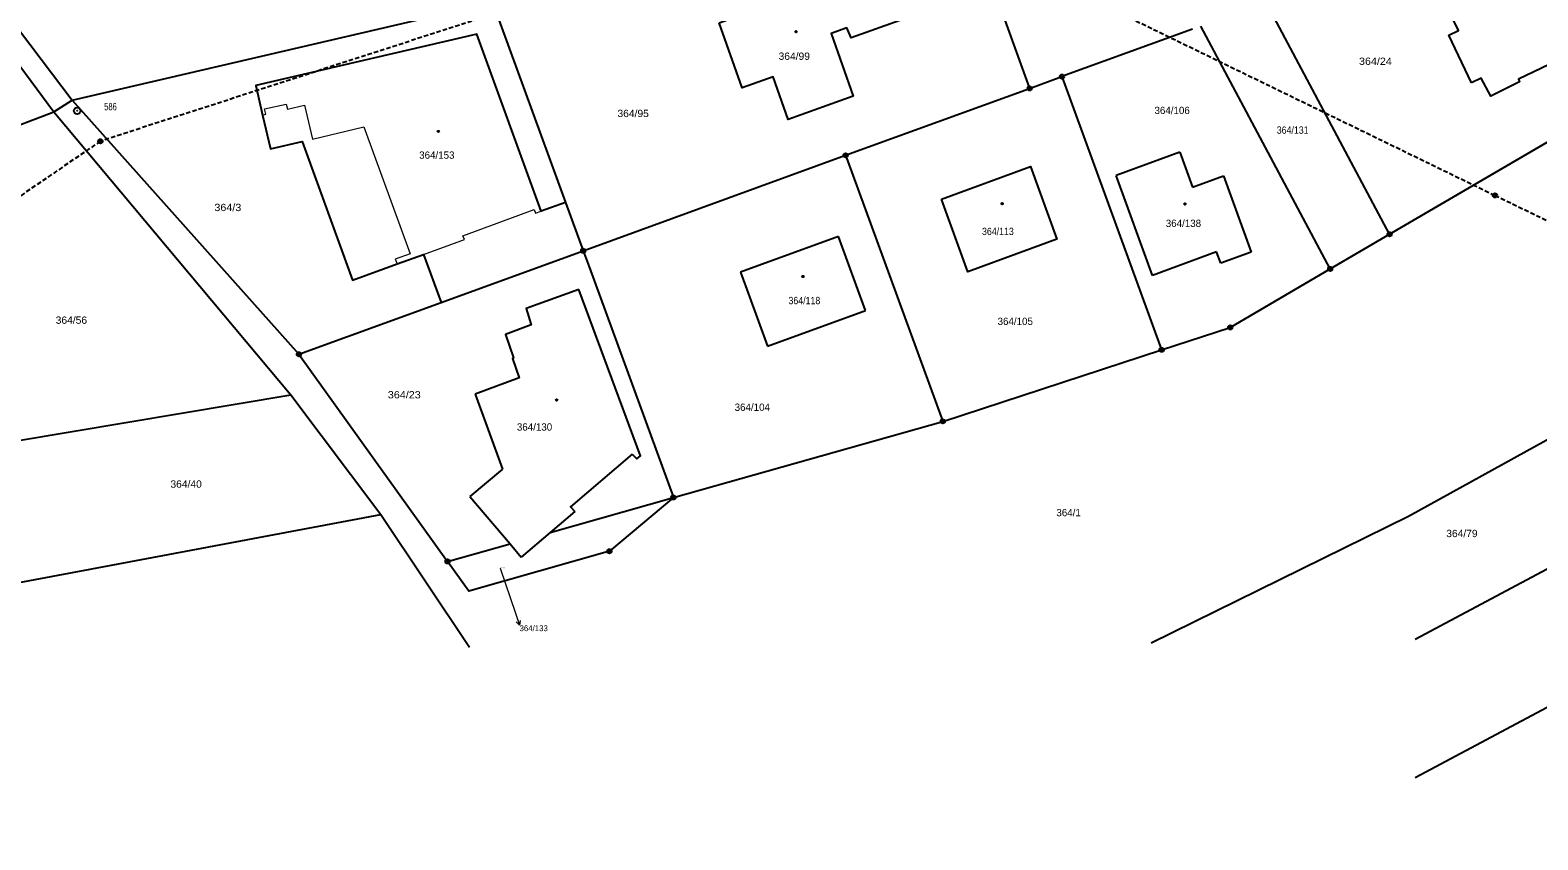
# Model space of a CAD drawing. Extents: x -592965 to -592390, y -1145071 to -1144631.
# Drawn here: x -592769.5 to -592594.1, y -1145071.2 to -1144977 of the extents above; entities that cross this region are included whole.
import ezdxf
from ezdxf.enums import TextEntityAlignment as Align

# ---------------------------------------------------------------- set-up
doc = ezdxf.new("R2010")
doc.units = 0
doc.header["$LTSCALE"] = 0.17
doc.linetypes.add('MEDIUM_DASHED', pattern=[4.5, 3, -1.5])
doc.layers.add('4', color=7, linetype='Continuous', lineweight=25)

msp = doc.modelspace()

# ---------------------------------------------------------------- linework, layer by layer
at = {"layer": '4'}
for p, q in [((-592662.36, -1144958.47), (-592653.19, -1144983.74)), ((-592775.53, -1144974.54), (-592766.72, -1144986.47)), ((-592618.23, -1145004.75), (-592633.27, -1144976.49)), ((-592634.25, -1144976.85), (-592649.43, -1144982.37)), ((-592674.6, -1144991.53), (-592653.19, -1144983.74)), ((-592653.19, -1144983.74), (-592649.43, -1144982.37)), ((-592649.43, -1144982.37), (-592637.84, -1145014.16)), ((-592766.72, -1144986.47), (-592764.58, -1144985.13)), ((-592764.58, -1144985.13), (-592738.2, -1145014.67)), ((-592784.27, -1144993.14), (-592766.72, -1144986.47)), ((-592766.72, -1144986.47), (-592739.14, -1145019.41)), ((-592611.32, -1145000.71), (-592591.61, -1144989.18)), ((-592705.13, -1145002.64), (-592674.6, -1144991.53)), ((-592635.71, -1144991.18), (-592643.11, -1144993.87)), ((-592635.71, -1144991.18), (-592634.23, -1144995.22)), ((-592638.9, -1145005.53), (-592643.11, -1144993.87)), ((-592634.23, -1144995.22), (-592630.65, -1144993.92)), ((-592630.65, -1144993.92), (-592627.42, -1145002.8)), ((-592707.19, -1144997), (-592710, -1144998.03)), ((-592675.42, -1145000.98), (-592686.83, -1145005.13)), ((-592672.29, -1145009.57), (-592675.42, -1145000.98)), ((-592631.45, -1145002.77), (-592638.9, -1145005.53)), ((-592630.96, -1145004.09), (-592631.45, -1145002.77)), ((-592627.42, -1145002.8), (-592630.96, -1145004.09)), ((-592686.83, -1145005.13), (-592683.7, -1145013.73)), ((-592683.7, -1145013.73), (-592672.29, -1145009.57)), ((-592738.2, -1145014.67), (-592720.91, -1145038.78)), ((-592771.06, -1145024.76), (-592739.14, -1145019.41)), ((-592739.14, -1145019.41), (-592728.67, -1145033.3)), ((-592717.7, -1145019.32), (-592714.53, -1145028.03)), ((-592608.34, -1145047.82), (-592558.85, -1145021.44)), ((-592714.53, -1145028.03), (-592718.31, -1145031.21)), ((-592608.36, -1145063.93), (-592546.61, -1145030.99)), ((-592718.31, -1145031.21), (-592713.63, -1145036.72)), ((-592708.98, -1145035.4), (-592694.63, -1145031.34)), ((-592819.84, -1145050.47), (-592728.67, -1145033.3)), ((-592728.67, -1145033.3), (-592718.36, -1145048.77)), ((-592706.11, -1145032.97), (-592708.98, -1145035.4)), ((-592708.98, -1145035.4), (-592712.36, -1145038.27)), ((-592720.91, -1145038.78), (-592713.63, -1145036.72)), ((-592713.63, -1145036.72), (-592712.36, -1145038.27))]:
    msp.add_line(p, q, dxfattribs=at)
at = {"layer": '4', "linetype": 'MEDIUM_DASHED'}
for points in [[(-592857.7, -1144647.96), (-592827.25, -1144698.04), (-592798.73, -1144745.3), (-592765.1, -1144800.74), (-592721.92, -1144873.86), (-592693.51, -1144920.47), (-592669.72, -1144961.82), (-592709.34, -1144973.09), (-592761.29, -1144989.89), (-592825.83, -1145034.08), (-592878.88, -1145071.17)], [(-592669.72, -1144961.82), (-592599.07, -1144996.19), (-592537.81, -1145025.68), (-592483.65, -1145051.69)]]:
    msp.add_lwpolyline(points, dxfattribs=at)
at = {"layer": '4'}
for points in [[(-592601.78, -1144983.1), (-592604.44, -1144977.55), (-592603.32, -1144977.01), (-592605.06, -1144973.35), (-592601, -1144971.39), (-592600.86, -1144971.68), (-592596.51, -1144969.57), (-592596.55, -1144969.48), (-592592.72, -1144967.63), (-592588.6, -1144976.22), (-592592.06, -1144977.86), (-592590.98, -1144980.12), (-592596.32, -1144982.68), (-592596.19, -1144982.99), (-592599.54, -1144984.65), (-592600.66, -1144982.55)], [(-592689.32, -1144976.1), (-592668.32, -1144968.52), (-592665.99, -1144975.02), (-592673.94, -1144977.88), (-592674.44, -1144976.7), (-592676.29, -1144977.37), (-592673.71, -1144984.65), (-592681.27, -1144987.36), (-592683.04, -1144982.4), (-592686.63, -1144983.68)], [(-592663.45, -1144996.63), (-592653.1, -1144992.84), (-592650.02, -1145001.3), (-592660.37, -1145005.08)]]:
    msp.add_lwpolyline(points, close=True, dxfattribs=at)
for points in [[(-592773.14, -1144973.83), (-592764.58, -1144985.13), (-592715.69, -1144973.75)], [(-592715.69, -1144973.75), (-592707.19, -1144997), (-592705.13, -1145002.64)], [(-592611.32, -1145000.71), (-592624.43, -1144976.07), (-592624.75, -1144975.48)], [(-592710, -1144998.03), (-592717.51, -1144977.44), (-592743.21, -1144983.42), (-592742.44, -1144986.84), (-592741.52, -1144990.79), (-592737.83, -1144989.92), (-592731.95, -1145006.05), (-592726.78, -1145004.17), (-592723.7, -1145003.05), (-592721.65, -1145008.65)], [(-592674.6, -1144991.53), (-592673.91, -1144993.41), (-592663.29, -1145022.48)], [(-592629.85, -1145011.55), (-592618.23, -1145004.75), (-592611.32, -1145000.71)], [(-592738.2, -1145014.67), (-592721.65, -1145008.65), (-592705.13, -1145002.64)], [(-592705.13, -1145002.64), (-592704.44, -1145004.52), (-592694.63, -1145031.34)], [(-592705.64, -1145007.16), (-592711.77, -1145009.36), (-592711.16, -1145011.26), (-592714.18, -1145012.38), (-592713.25, -1145015.11), (-592713.35, -1145015.18), (-592712.56, -1145017.43), (-592717.7, -1145019.32)], [(-592699.41, -1145026.31), (-592698.88, -1145026.86), (-592698.46, -1145026.5), (-592705.64, -1145007.16)], [(-592694.63, -1145031.34), (-592663.29, -1145022.48), (-592637.84, -1145014.16), (-592629.85, -1145011.55)], [(-592639.04, -1145048.25), (-592609.13, -1145033.5), (-592572.24, -1145013.15)], [(-592699.41, -1145026.31), (-592706.62, -1145032.42), (-592706.11, -1145032.97)], [(-592694.63, -1145031.34), (-592702.07, -1145037.6), (-592718.43, -1145042.24), (-592720.91, -1145038.78)]]:
    msp.add_lwpolyline(points, dxfattribs=at)
at = {"layer": '4', "lineweight": 13}
for points in [[(-592742.44, -1144986.84), (-592742.04, -1144986.75), (-592742.18, -1144986.13), (-592739.66, -1144985.56), (-592739.52, -1144986.16), (-592737.53, -1144985.71), (-592736.63, -1144989.64), (-592730.63, -1144988.22), (-592725.25, -1145002.99), (-592726.98, -1145003.61), (-592726.78, -1145004.17)], [(-592723.7, -1145003.05), (-592718.94, -1145001.31), (-592719.11, -1145000.88), (-592710.81, -1144997.85), (-592710.66, -1144998.26), (-592710, -1144998.03)], [(-592714.8, -1145039.58), (-592713.014, -1145044.791), (-592712.528, -1145046.21)], [(-592712.453, -1145045.656), (-592712.528, -1145046.21), (-592712.926, -1145045.818)]]:
    msp.add_lwpolyline(points, dxfattribs=at)
at = {"layer": '4'}
for centre, radius in [((-592680.36, -1144977.14), 0.0875), ((-592653.19, -1144983.74), 0.25), ((-592653.19, -1144983.74), 0.0164), ((-592649.43, -1144982.37), 0.25), ((-592649.43, -1144982.37), 0.0164), ((-592763.99, -1144986.35), 0.375), ((-592763.99, -1144986.35), 0.0164), ((-592721.97, -1144988.75), 0.0875), ((-592761.29, -1144989.89), 0.25), ((-592761.29, -1144989.89), 0.15), ((-592761.29, -1144989.89), 0.075), ((-592674.6, -1144991.53), 0.25), ((-592674.6, -1144991.53), 0.0164), ((-592599.07, -1144996.19), 0.25), ((-592599.07, -1144996.19), 0.15), ((-592599.07, -1144996.19), 0.075), ((-592656.39, -1144997.15), 0.0875), ((-592635.12, -1144997.2), 0.0875), ((-592611.32, -1145000.71), 0.25), ((-592611.32, -1145000.71), 0.0164), ((-592705.13, -1145002.64), 0.25), ((-592705.13, -1145002.64), 0.0164), ((-592618.23, -1145004.75), 0.25), ((-592618.23, -1145004.75), 0.0164), ((-592679.55, -1145005.63), 0.0875), ((-592629.85, -1145011.55), 0.25), ((-592629.85, -1145011.55), 0.0164), ((-592738.2, -1145014.67), 0.25), ((-592738.2, -1145014.67), 0.0164), ((-592637.84, -1145014.16), 0.25), ((-592637.84, -1145014.16), 0.0164), ((-592708.22, -1145020), 0.0875), ((-592663.29, -1145022.48), 0.25), ((-592663.29, -1145022.48), 0.0164), ((-592694.63, -1145031.34), 0.25), ((-592694.63, -1145031.34), 0.0164), ((-592702.07, -1145037.6), 0.25), ((-592702.07, -1145037.6), 0.0164), ((-592720.91, -1145038.78), 0.25), ((-592720.91, -1145038.78), 0.0164)]:
    msp.add_circle(centre, radius, dxfattribs=at)

# ---------------------------------------------------------------- texts
for s, height, width, p in [('364/99', 0.85, 1.05, (-592682.397, -1144980.42)), ('364/24', 0.85, 1.1, (-592614.88, -1144981.01)), ('364/95', 0.85, 1.05, (-592701.138, -1144987.08)), ('364/131', 0.85, 0.9, (-592624.443, -1144989.02)), ('364/3', 0.85, 1.1, (-592748.03, -1144998.02)), ('364/113', 0.85, 0.9, (-592658.733, -1145000.81)), ('364/118', 0.85, 0.9, (-592681.243, -1145008.85)), ('364/56', 0.85, 1.05, (-592766.49, -1145011.13)), ('364/23', 0.85, 1.1, (-592727.85, -1145019.81)), ('364/40', 0.85, 1.05, (-592753.14, -1145030.2)), ('364/79', 0.85, 1.05, (-592604.73, -1145035.95)), ('364/133', 0.1, 1.15, (-592714.8, -1145039.58))]:
    msp.add_text(s, height=height, dxfattribs=dict(at, width=width)).set_placement(p)
at = {"layer": '4', "width": 0.75}
msp.add_text('586', height=0.85, dxfattribs=at).set_placement((-592759.379, -1144986.285), align=Align.RIGHT)
at = {"layer": '4'}
for s, height, p in [('364/106', 0.85, (-592638.669, -1144986.73)), ('364/153', 0.85, (-592724.207, -1144991.93)), ('364/138', 0.85, (-592637.355, -1144999.865)), ('364/105', 0.85, (-592656.92, -1145011.27)), ('364/104', 0.85, (-592687.509, -1145021.26)), ('364/130', 0.85, (-592712.84, -1145023.56)), ('364/1', 0.85, (-592650.08, -1145033.52)), ('364/133', 0.68, (-592712.528, -1145046.89))]:
    msp.add_text(s, height=height, dxfattribs=at).set_placement(p)

doc.saveas('drawing.dxf')
